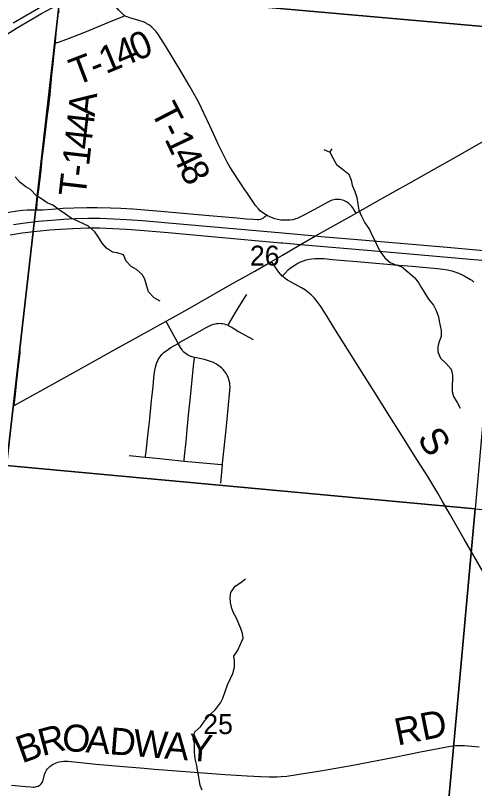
# Model space of a CAD drawing. Extents: x 0 to 34, y 0 to 22.
# Drawn here: x 3.909 to 4.873, y 14.717 to 16.342 of the extents above; entities that cross this region are included whole.
import ezdxf

# ---------------------------------------------------------------- set-up
doc = ezdxf.new("R2010")
doc.units = 0
for name, color, linetype in [('GM_X_County_Road', 7, 'Continuous'), ('GM_X_County_Road_Text', 7, 'Continuous'), ('GM_X_Interstate_Route', 7, 'Continuous'), ('GM_X_Minor_River', 7, 'Continuous'), ('GM_X_Rail_Line', 7, 'Continuous'), ('GM_X_Section', 7, 'Continuous'), ('GM_X_Section_Text', 7, 'Continuous'), ('GM_X_Township_Road', 7, 'Continuous'), ('GM_X_Township_Road_Text', 7, 'Continuous')]:
    doc.layers.add(name, color=color, linetype=linetype)

msp = doc.modelspace()

# ---------------------------------------------------------------- linework, layer by layer
at = {"layer": 'GM_X_County_Road'}
for points in [[(4.6243, 15.9265), (4.652, 15.9425), (4.7017, 15.9701), (4.7345, 15.9885), (4.7768, 16.0126), (4.8276, 16.0414), (4.9914, 16.134)], [(4.4464, 15.8247), (4.4691, 15.8377), (4.5036, 15.8584), (4.5074, 15.8606), (4.5389, 15.8785), (4.5688, 15.8955), (4.6191, 15.9234), (4.6243, 15.9265)], [(4.2249, 15.6993), (4.2325, 15.7035), (4.2704, 15.7248), (4.3218, 15.7538), (4.3596, 15.7754), (4.411, 15.8045), (4.4464, 15.8247)], [(4.4689, 15.7941), (4.4656, 15.7974), (4.4616, 15.802), (4.4579, 15.807), (4.4512, 15.8173), (4.4464, 15.8247)], [(4.8918, 15.1712), (4.8713, 15.206), (4.851, 15.2409), (4.82, 15.2948), (4.805, 15.322), (4.7956, 15.3381), (4.7744, 15.3725), (4.7529, 15.4067), (4.7165, 15.4645), (4.6932, 15.5013), (4.6668, 15.5434), (4.6405, 15.5855), (4.6057, 15.6407), (4.581, 15.6802), (4.5597, 15.7145), (4.5496, 15.7302), (4.5423, 15.7404), (4.5363, 15.7476), (4.5297, 15.7543), (4.5226, 15.7604), (4.5176, 15.7642), (4.5096, 15.7692), (4.4877, 15.7809), (4.4797, 15.7857), (4.4747, 15.7892), (4.47, 15.7931), (4.4689, 15.7941)], [(3.9058, 15.522), (3.9664, 15.5555), (4.0169, 15.5836), (4.0723, 15.6143), (4.1238, 15.6432), (4.1483, 15.6568), (4.2249, 15.6993)]]:
    msp.add_lwpolyline(points, dxfattribs=at)
at = {"layer": 'GM_X_Interstate_Route'}
for points in [[(3.9042, 15.9025), (3.9288, 15.906), (3.9565, 15.9092), (3.9843, 15.9118), (4.0091, 15.9136), (4.0339, 15.9148), (4.0618, 15.9154), (4.0866, 15.9154), (4.1146, 15.9146), (4.1417, 15.9132), (4.1754, 15.9106), (4.2539, 15.9038), (4.4694, 15.8846)], [(3.8977, 15.881), (3.9223, 15.8846), (3.9532, 15.8882), (3.981, 15.891), (4.0034, 15.8928), (4.0291, 15.8941), (4.0607, 15.8951), (4.0847, 15.8951), (4.1127, 15.8943), (4.1414, 15.8928), (4.1704, 15.8904), (4.2292, 15.8853), (4.3282, 15.8768), (4.4661, 15.8641), (4.4701, 15.8638)], [(4.4694, 15.8846), (4.5389, 15.8785), (4.5509, 15.8774), (4.6352, 15.8704), (4.8152, 15.8545), (4.8766, 15.8491), (4.9718, 15.8409), (5.087, 15.8306), (5.1797, 15.8225), (5.282, 15.8136), (5.3227, 15.8103), (5.3626, 15.8077), (5.4014, 15.806), (5.4428, 15.8049), (5.4852, 15.8044), (5.5227, 15.8046), (5.5606, 15.8054), (5.5978, 15.807), (5.6405, 15.8094)], [(4.4701, 15.8638), (4.5074, 15.8606), (4.5483, 15.8571), (4.639, 15.8493), (4.7133, 15.8429), (4.8636, 15.8295), (4.9707, 15.8203), (5.1248, 15.8069), (5.2055, 15.7999), (5.2844, 15.7931), (5.3244, 15.7899), (5.3512, 15.7881), (5.3951, 15.7859), (5.4291, 15.7849), (5.4653, 15.7843), (5.4878, 15.7839), (5.5274, 15.7845), (5.5654, 15.7855), (5.6127, 15.7873), (5.6507, 15.7897)]]:
    msp.add_lwpolyline(points, dxfattribs=at)
at = {"layer": 'GM_X_Minor_River'}
for points in [[(4.5565, 16.06), (4.569, 16.0542), (4.5756, 16.0412), (4.5827, 16.0282), (4.5951, 16.0193), (4.6087, 16.0082), (4.6138, 15.9956), (4.616, 15.9849), (4.6211, 15.9719), (4.6259, 15.959), (4.628, 15.9449), (4.6301, 15.9324), (4.6353, 15.9198), (4.6423, 15.9056), (4.6521, 15.8918), (4.6583, 15.8781), (4.6635, 15.8686), (4.6698, 15.8548), (4.6761, 15.8433), (4.6847, 15.8322), (4.6956, 15.8226), (4.7074, 15.8175), (4.7195, 15.8144), (4.733, 15.8032), (4.7477, 15.7905), (4.7559, 15.779), (4.7615, 15.7695), (4.7682, 15.7584), (4.7764, 15.7457), (4.7865, 15.7327), (4.7924, 15.722), (4.7972, 15.7087), (4.7986, 15.6992), (4.8007, 15.6896), (4.8029, 15.6797), (4.8027, 15.6672), (4.7977, 15.6547), (4.796, 15.6453), (4.7959, 15.635), (4.801, 15.6213), (4.8127, 15.6113), (4.8239, 15.5983), (4.8268, 15.5861), (4.8267, 15.5758), (4.8258, 15.5652), (4.826, 15.5515), (4.8285, 15.5409), (4.836, 15.5286), (4.8423, 15.5164)], [(4.569, 16.0542), (4.5736, 16.0617)], [(4.2126, 15.7413), (4.1998, 15.7483), (4.1878, 15.761), (4.1845, 15.7728), (4.1801, 15.7877), (4.1749, 15.7972), (4.1629, 15.808), (4.1512, 15.8142), (4.1407, 15.8253), (4.1352, 15.8383), (4.1223, 15.8426), (4.1121, 15.8443), (4.0996, 15.8524), (4.0903, 15.8635), (4.0817, 15.8777), (4.075, 15.8872), (4.0622, 15.8992), (4.0517, 15.9035), (4.0392, 15.9093), (4.0256, 15.9156), (4.0135, 15.9244), (4, 15.9333), (3.9868, 15.9433), (3.9751, 15.9477), (3.9653, 15.9546), (3.9517, 15.9635), (3.9401, 15.9758), (3.9303, 15.9816), (3.9186, 15.9905), (3.9078, 16.0028)], [(4.301, 14.7133), (4.2966, 14.7232), (4.2952, 14.7327), (4.2927, 14.7453), (4.2909, 14.7556), (4.2895, 14.7655), (4.2859, 14.7792), (4.2849, 14.7925), (4.2844, 14.8122), (4.2815, 14.8225), (4.285, 14.8361), (4.2973, 14.8466), (4.307, 14.8606), (4.3174, 14.8726), (4.3289, 14.8831), (4.3393, 14.897), (4.344, 14.9072), (4.3491, 14.9212), (4.3542, 14.9348), (4.3605, 14.948), (4.3652, 14.959), (4.3688, 14.9718), (4.3685, 14.9855), (4.3671, 14.9954), (4.3749, 15.0067), (4.3815, 15.0203), (4.387, 15.0331), (4.3856, 15.0426), (4.3819, 15.0533), (4.3779, 15.0632), (4.3719, 15.0766), (4.3664, 15.0861), (4.3631, 15.0957), (4.3602, 15.1082), (4.3592, 15.1185), (4.3612, 15.1287), (4.3697, 15.1423), (4.382, 15.1501), (4.3916, 15.1576)]]:
    msp.add_lwpolyline(points, dxfattribs=at)
at = {"layer": 'GM_X_Rail_Line'}
for points in [[(3.9037, 16.3265), (3.9568, 16.3573), (3.9994, 16.3802), (4.0431, 16.4012), (4.0942, 16.4234), (4.2212, 16.476), (4.3504, 16.5292), (4.4673, 16.5775), (4.5622, 16.616), (4.5913, 16.6262), (4.6186, 16.6344), (4.6681, 16.6486), (4.704, 16.6605), (4.7328, 16.671), (4.7714, 16.6872)], [(2.932, 15.6459), (3.0706, 15.7414), (3.1519, 15.7974), (3.2602, 15.8725), (3.4157, 15.9792), (3.549, 16.0708), (3.8394, 16.2704), (3.9107, 16.3151), (3.9634, 16.3457), (4.0055, 16.3683), (4.0487, 16.3891), (4.0994, 16.4111), (4.2263, 16.4637), (4.3555, 16.5169), (4.4723, 16.5652), (4.704, 16.6605)]]:
    msp.add_lwpolyline(points, dxfattribs=at)
at = {"layer": 'GM_X_Section'}
for points in [[(4.0957, 17.4007), (5.0487, 17.3219), (4.9634, 16.3122), (4.0036, 16.3979)], [(2.9781, 16.4922), (4.0036, 16.3979), (3.89, 15.3957), (2.8777, 15.4895)], [(4.0036, 16.3979), (4.9634, 16.3122), (4.8743, 15.3051), (3.89, 15.3957)], [(3.89, 15.3957), (4.8743, 15.3051), (4.7835, 14.3098), (3.8021, 14.3916), (3.7885, 14.3929)], [(4.8743, 15.3051), (5.8825, 15.2209), (5.7982, 14.227), (4.7952, 14.3092), (4.7835, 14.3098)]]:
    msp.add_lwpolyline(points, close=True, dxfattribs=at)
at = {"layer": 'GM_X_Township_Road'}
for p, q in [((4.1476, 15.417), (4.1817, 15.4136)), ((4.3398, 15.3587), (4.3433, 15.3974))]:
    msp.add_line(p, q, dxfattribs=at)
for points in [[(4.1378, 16.3414), (4.136, 16.3426), (4.1335, 16.3448), (4.1295, 16.3485), (4.1253, 16.353), (4.1213, 16.3578), (4.1178, 16.3627), (4.113, 16.3707), (4.1116, 16.3735), (4.1102, 16.3765), (4.1088, 16.3793), (4.1076, 16.3821), (4.1063, 16.385), (4.0992, 16.406), (4.0967, 16.415), (4.0958, 16.4179), (4.0947, 16.4207), (4.0933, 16.4233), (4.0916, 16.4257), (4.0905, 16.4265), (4.0887, 16.4275)], [(3.9923, 16.2851), (3.9924, 16.2865), (3.9945, 16.3113), (3.9957, 16.3242), (3.9966, 16.3336), (3.9974, 16.3387), (3.9979, 16.342), (3.999, 16.3467), (4.0002, 16.3513)], [(3.9923, 16.2851), (3.9942, 16.2851), (3.9966, 16.2851), (3.9992, 16.2854), (4.0164, 16.2917), (4.054, 16.3063), (4.0796, 16.317), (4.1048, 16.3276), (4.1235, 16.3354), (4.1358, 16.3405), (4.1378, 16.3414)], [(4.3929, 15.9715), (4.3918, 15.9732), (4.3649, 16.014), (4.3588, 16.0237), (4.3532, 16.0336), (4.3462, 16.0474), (4.3353, 16.07), (4.3287, 16.0841), (4.3169, 16.1094), (4.305, 16.1347), (4.2928, 16.1599), (4.2841, 16.1762), (4.2749, 16.1925), (4.2557, 16.2244), (4.2237, 16.2777), (4.214, 16.2936), (4.2088, 16.3012), (4.2033, 16.3086), (4.1992, 16.3131), (4.1946, 16.3172), (4.1898, 16.321), (4.1847, 16.3244), (4.182, 16.3259), (4.1764, 16.3283), (4.1676, 16.3311), (4.1559, 16.3346), (4.1486, 16.3369), (4.1449, 16.3381), (4.1428, 16.3388), (4.1404, 16.3398), (4.1386, 16.3409), (4.1378, 16.3414)], [(3.9532, 15.9334), (3.9544, 15.9484), (3.9558, 15.9617), (3.9569, 15.9709), (3.958, 15.98), (3.959, 15.9889), (3.9601, 15.998), (3.9616, 16.0102), (3.9622, 16.016), (3.9626, 16.0189), (3.9629, 16.022), (3.9632, 16.025), (3.9639, 16.0311), (3.9642, 16.0341), (3.9648, 16.0402), (3.9666, 16.0555), (3.9725, 16.1017), (3.9746, 16.1202), (3.9761, 16.1325), (3.9783, 16.151), (3.9811, 16.1757), (3.9851, 16.2159), (3.9877, 16.2405), (3.9905, 16.2681), (3.9923, 16.2851)], [(4.4359, 15.9218), (4.4335, 15.9231), (4.4283, 15.9267), (4.4235, 15.9307), (4.419, 15.9352), (4.413, 15.9424), (4.4057, 15.9525), (4.3929, 15.9715)], [(4.6243, 15.9265), (4.6203, 15.9325), (4.6169, 15.9377), (4.6151, 15.9401), (4.6131, 15.9425), (4.611, 15.9447), (4.6087, 15.9467), (4.6063, 15.9485), (4.6037, 15.9502), (4.6011, 15.9516), (4.5983, 15.9528), (4.5954, 15.9538), (4.5925, 15.9545), (4.5895, 15.955), (4.5865, 15.9552), (4.5835, 15.9552), (4.5804, 15.9549), (4.5775, 15.9544), (4.5745, 15.9536), (4.5716, 15.9527), (4.566, 15.9502), (4.5442, 15.9384), (4.5171, 15.9231), (4.5087, 15.9189), (4.5001, 15.9151), (4.4972, 15.914), (4.491, 15.9125), (4.4848, 15.9116), (4.4785, 15.9112), (4.4722, 15.9112), (4.4701, 15.9114)], [(3.9532, 15.9334), (3.9578, 15.9333), (3.9619, 15.9333), (3.9661, 15.9334), (3.9846, 15.9349), (4.0084, 15.9365), (4.0308, 15.9374), (4.0587, 15.9381), (4.0804, 15.9381), (4.1084, 15.9377), (4.13, 15.9368), (4.1548, 15.9352), (4.2136, 15.9302), (4.3156, 15.9214), (4.3743, 15.9163), (4.3929, 15.9145), (4.4084, 15.9134), (4.416, 15.913), (4.4193, 15.9132), (4.4232, 15.9138), (4.4259, 15.9145), (4.4277, 15.9154), (4.4293, 15.9164), (4.4318, 15.9184), (4.4337, 15.92), (4.4359, 15.9218)], [(3.7751, 15.925), (3.7824, 15.9269), (3.7872, 15.9277), (3.7906, 15.9278), (3.7943, 15.9277), (3.7973, 15.9273), (3.8002, 15.9266), (3.806, 15.9248), (3.8145, 15.9214), (3.8233, 15.9183), (3.8264, 15.9176), (3.8297, 15.9173), (3.8328, 15.9175), (3.8359, 15.9179), (3.8907, 15.9275), (3.912, 15.931), (3.9242, 15.9325), (3.9334, 15.9332), (3.9431, 15.9334), (3.9532, 15.9334)], [(4.4701, 15.9114), (4.4659, 15.9117), (4.4597, 15.9127), (4.4536, 15.9143), (4.4448, 15.9175), (4.439, 15.92), (4.4359, 15.9218)], [(4.4689, 15.7941), (4.4748, 15.8003), (4.4814, 15.807), (4.486, 15.8112), (4.4937, 15.8164), (4.5018, 15.821), (4.5074, 15.8237), (4.5132, 15.826), (4.5191, 15.8279), (4.5251, 15.8295), (4.5312, 15.8305), (4.5374, 15.8311), (4.5436, 15.8312), (4.556, 15.8307), (4.5746, 15.8291), (4.6427, 15.8232), (4.7045, 15.8177), (4.7417, 15.8146), (4.7943, 15.8099), (4.8066, 15.8086), (4.8158, 15.8072), (4.8249, 15.8052), (4.8338, 15.8024), (4.8424, 15.7988), (4.8507, 15.7946), (4.8641, 15.7868), (4.8668, 15.7852), (4.8692, 15.7833), (4.8713, 15.7811)], [(4.3553, 15.6904), (4.3563, 15.6923), (4.371, 15.7177), (4.3819, 15.7359), (4.3906, 15.7489), (4.3948, 15.7556)], [(4.25, 15.6526), (4.2487, 15.6548), (4.2367, 15.6766), (4.2261, 15.697), (4.2249, 15.6993)], [(4.25, 15.6526), (4.2538, 15.6548), (4.2754, 15.667), (4.2943, 15.6776), (4.3105, 15.6865), (4.3189, 15.6905), (4.3248, 15.6927), (4.3279, 15.6936), (4.331, 15.6943), (4.3342, 15.6946), (4.3373, 15.6947), (4.3405, 15.6946), (4.3437, 15.6941), (4.3472, 15.6933), (4.3505, 15.6924), (4.3536, 15.6912), (4.3553, 15.6904)], [(4.3553, 15.6904), (4.3584, 15.6887), (4.3639, 15.6857), (4.3771, 15.6777), (4.3913, 15.6697), (4.3988, 15.6656), (4.4075, 15.6609)], [(4.1817, 15.4136), (4.1819, 15.4158), (4.1834, 15.4308), (4.185, 15.446), (4.1878, 15.4709), (4.1898, 15.4871), (4.1945, 15.5323), (4.1952, 15.5378), (4.1976, 15.5618), (4.1993, 15.5803), (4.2008, 15.5922), (4.2029, 15.6029), (4.2044, 15.6077), (4.2058, 15.6123), (4.2067, 15.6148), (4.2086, 15.6185), (4.2104, 15.6214), (4.212, 15.6239), (4.214, 15.6266), (4.2165, 15.6298), (4.22, 15.6335), (4.2248, 15.637), (4.2351, 15.6438), (4.25, 15.6526)], [(4.2845, 15.6232), (4.2819, 15.6238), (4.2757, 15.626), (4.27, 15.6287), (4.2674, 15.6303), (4.2648, 15.6321), (4.2625, 15.6341), (4.2603, 15.6363), (4.2584, 15.6388), (4.2549, 15.6439), (4.25, 15.6526)], [(3.9058, 15.522), (3.9066, 15.5274), (3.9086, 15.5459), (3.9115, 15.5737), (3.9148, 15.6045), (3.9181, 15.6323), (3.9186, 15.6385)], [(4.2627, 15.4052), (4.2628, 15.4064), (4.2636, 15.4153), (4.2669, 15.4463), (4.2694, 15.4719), (4.2729, 15.5088), (4.2755, 15.533), (4.2834, 15.6119), (4.2843, 15.6211), (4.2845, 15.6232)], [(4.3433, 15.3974), (4.3435, 15.4001), (4.3489, 15.4519), (4.3516, 15.4788), (4.3556, 15.516), (4.359, 15.5534), (4.3594, 15.5603), (4.3591, 15.5657), (4.3586, 15.5689), (4.3576, 15.5741), (4.3566, 15.5773), (4.3553, 15.5808), (4.3538, 15.5846), (4.3518, 15.5883), (4.3498, 15.5912), (4.3474, 15.5942), (4.3447, 15.5974), (4.3417, 15.6005), (4.3384, 15.6034), (4.3337, 15.607), (4.3297, 15.6096), (4.3246, 15.6122), (4.3203, 15.6141), (4.3162, 15.6155), (4.3121, 15.6168), (4.3053, 15.6184), (4.2952, 15.6206), (4.2887, 15.6221), (4.2845, 15.6232)], [(4.1817, 15.4136), (4.2048, 15.4113), (4.2569, 15.4057), (4.2627, 15.4052)], [(4.2627, 15.4052), (4.318, 15.3998), (4.341, 15.3977), (4.3433, 15.3974)], [(3.9003, 14.7239), (3.9302, 14.7212), (3.9409, 14.7203), (3.9454, 14.7201), (3.9477, 14.7202), (3.9505, 14.7207), (3.9528, 14.7213), (3.9559, 14.7223), (3.9584, 14.7237), (3.9606, 14.7252), (3.9626, 14.727), (3.9643, 14.7295), (3.9657, 14.7321), (3.9668, 14.7348), (3.9696, 14.7469), (3.9706, 14.75), (3.972, 14.7529), (3.9737, 14.7556), (3.9761, 14.7587), (3.9781, 14.7608), (3.9806, 14.7632), (3.9844, 14.7661), (3.9878, 14.7682), (3.991, 14.7699), (3.9942, 14.7714), (3.9973, 14.7724), (4.0006, 14.7732), (4.005, 14.7739), (4.0098, 14.7743), (4.0182, 14.7744), (4.0524, 14.771), (4.0771, 14.7686), (4.1356, 14.7636), (4.1789, 14.7598), (4.2006, 14.7581), (4.2284, 14.7557), (4.247, 14.7541), (4.349, 14.7467), (4.3953, 14.7439), (4.4231, 14.7423), (4.4417, 14.7416), (4.4572, 14.7416), (4.4664, 14.7421), (4.4787, 14.7433), (4.5002, 14.7465), (4.5492, 14.7544), (4.6134, 14.7658), (4.6683, 14.7759), (4.7048, 14.783), (4.7596, 14.7939), (4.8114, 14.804), (4.8267, 14.8067), (4.8329, 14.8074), (4.8392, 14.8076), (4.8516, 14.8072), (4.8826, 14.805)]]:
    msp.add_lwpolyline(points, dxfattribs=at)

# ---------------------------------------------------------------- texts
at = {"layer": 'GM_X_County_Road_Text'}
msp.add_text('S', height=0.0568, rotation=302.6588, dxfattribs=at).set_placement((4.751, 15.4531))
at = {"layer": 'GM_X_Section_Text'}
for s, p in [('26', (4.401, 15.8161)), ('25', (4.303, 14.8315))]:
    msp.add_text(s, height=0.04186, rotation=0, dxfattribs=at).set_placement(p)
at = {"layer": 'GM_X_Township_Road_Text'}
for s, height, rotation, p in [('4', 0.0568, 22.7482, (4.1306, 16.2316)), ('0', 0.0568, 22.7539, (4.1627, 16.245)), ('1', 0.0568, 22.5123, (4.0983, 16.2182)), ('T', 0.0568, 20.9128, (4.0356, 16.1938)), ('-', 0.0568, 21.7639, (4.0761, 16.2093)), ('A', 0.0568, 83.5872, (4.0748, 16.1277)), ('T', 0.0568, 297.3346, (4.1913, 16.1408)), ('4', 0.0568, 83.5399, (4.0709, 16.0931)), ('4', 0.0568, 83.4729, (4.0669, 16.0585)), ('-', 0.0568, 295.7342, (4.2106, 16.1034)), ('1', 0.0568, 295.3687, (4.2207, 16.0825)), ('1', 0.0568, 83.44, (4.063, 16.024)), ('4', 0.0568, 295.3965, (4.2357, 16.0508)), ('8', 0.0568, 296.4889, (4.2513, 16.0181)), ('-', 0.0568, 83.421, (4.0603, 16.001)), ('T', 0.0568, 83.4171, (4.0555, 15.9589)), ('RD', 0.05682, 11.4061, (4.7111, 14.8071)), ('R', 0.0568, 14.786, (3.9649, 14.7849)), ('O', 0.0568, 356.4023, (4.0052, 14.7964)), ('B', 0.0568, 19.6817, (3.9222, 14.7696)), ('A', 0.0568, 355.4929, (4.0549, 14.7932)), ('D', 0.0568, 355.4856, (4.1047, 14.7893)), ('W', 0.0568, 355.4865, (4.1546, 14.7854)), ('A', 0.0568, 355.4881, (4.2202, 14.7802)), ('Y', 0.0568, 355.4856, (4.2701, 14.7763))]:
    msp.add_text(s, height=height, rotation=rotation, dxfattribs=at).set_placement(p)

doc.saveas('drawing.dxf')
